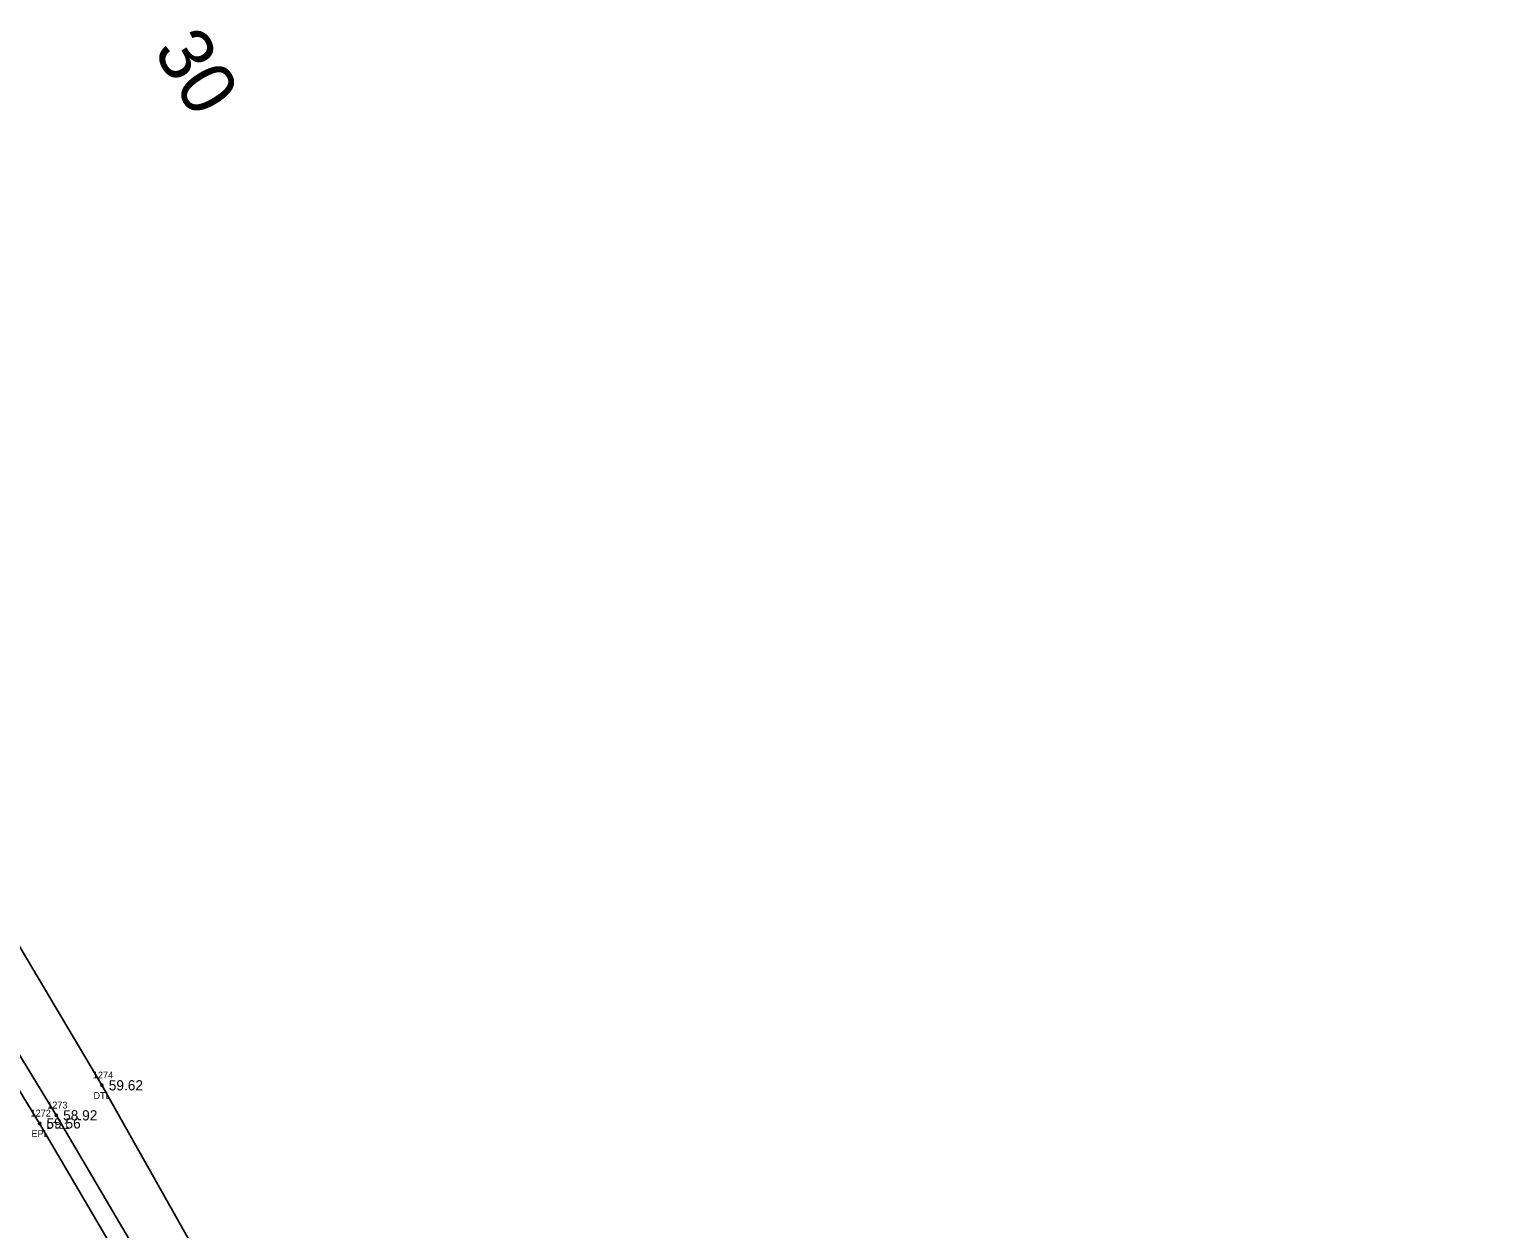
# Model space of a CAD drawing. Extents: x 2396531 to 2397633, y 770203 to 772837.
# Drawn here: x 2397369.7 to 2397586.1, y 770713.7 to 770889.5 of the extents above; entities that cross this region are included whole.
import ezdxf

# ---------------------------------------------------------------- set-up
doc = ezdxf.new("R2010")
doc.units = 0
for name, color, linetype in [('RD_EX_H2O', 7, 'Continuous'), ('RD_EX_H2O_txCode', 7, 'Continuous'), ('RD_EX_Road', 7, 'Continuous'), ('RD_EX_Road_txCode', 7, 'Continuous'), ('RD_EX_TX_H2O_ELEV', 7, 'Continuous'), ('RD_EX_TX_Road_ELEV', 7, 'Continuous'), ('RD_HC_TX_Sta50', 7, 'Continuous'), ('RD_SMD_Locator', 7, 'Continuous')]:
    doc.layers.add(name, color=color, linetype=linetype)

msp = doc.modelspace()

# ---------------------------------------------------------------- linework, layer by layer
at = {"layer": 'RD_EX_H2O'}
for points in [[(2397586.15, 770211.51), (2397567.31, 770287.61), (2397548.79, 770357.79), (2397525.19, 770434.22), (2397495.53, 770510.39), (2397465.51, 770576.5), (2397430.55, 770645.5), (2397380.29, 770734.7), (2397327.01, 770824.44), (2397291.42, 770882.36)], [(2397579.43, 770209.93), (2397561.1, 770285.3), (2397543.19, 770356.19), (2397518.98, 770431.67), (2397489.88, 770507.8), (2397460.56, 770573.86), (2397425.02, 770642.83), (2397373.6, 770730.3), (2397319.08, 770819.92), (2397284.14, 770878.8)]]:
    msp.add_lwpolyline(points, dxfattribs=at)
at = {"layer": 'RD_EX_Road'}
msp.add_lwpolyline([(2397576.88, 770209.21), (2397558.85, 770284.47), (2397539.93, 770354.87), (2397515.81, 770430.13), (2397486.97, 770506.75), (2397457.82, 770572.7), (2397422.37, 770641.75), (2397371.16, 770729.12), (2397316.57, 770818.52), (2397280.76, 770876.73)], dxfattribs=at)
at = {"layer": 'RD_SMD_Locator'}
for centre in [(2397380.29, 770734.7), (2397373.6, 770730.3), (2397371.16, 770729.12)]:
    msp.add_circle(centre, 0.15, dxfattribs=at)

# ---------------------------------------------------------------- texts
at = {"layer": 'RD_EX_H2O_txCode'}
for s, p in [('1274', (2397378.95, 770735.7)), ('1273', (2397372.26, 770731.3)), ('DTL', (2397379.05, 770732.7)), ('DTL1', (2397372.19, 770728.3))]:
    msp.add_text(s, height=1, dxfattribs=at).set_placement(p)
at = {"layer": 'RD_EX_Road_txCode'}
for s, p in [('1272', (2397369.82, 770730.12)), ('EPL', (2397369.96, 770727.12))]:
    msp.add_text(s, height=1, dxfattribs=at).set_placement(p)
at = {"layer": 'RD_EX_TX_H2O_ELEV'}
for s, p in [('59.62', (2397381.29, 770733.95)), ('58.92', (2397374.6, 770729.55))]:
    msp.add_text(s, height=1.5, dxfattribs=at).set_placement(p)
at = {"layer": 'RD_EX_TX_Road_ELEV'}
msp.add_text('59.56', height=1.5, dxfattribs=at).set_placement((2397372.16, 770728.37))
at = {"layer": 'RD_HC_TX_Sta50'}
msp.add_text('30', height=8, rotation=301.5082, dxfattribs=at).set_placement((2397387.7, 770886.36))

doc.saveas('drawing.dxf')
